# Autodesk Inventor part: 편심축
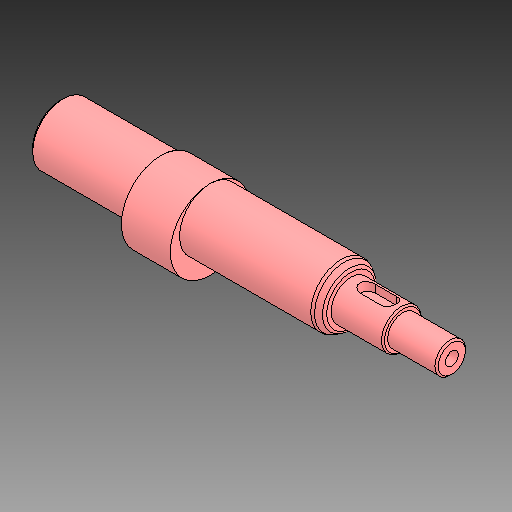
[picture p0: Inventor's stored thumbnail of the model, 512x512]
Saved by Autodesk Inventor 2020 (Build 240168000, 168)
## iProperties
Created: 2024-08
Part Number: 편심축
Material: 강철, 탄소
Document SubType Name: Modeling
Designer: 1강의실14
Density: 7.85 g/cm^3
Appearance: 기본값
Author: jhkim
Sending System: Autodesk Inventor 2025
Preprocessor: ST-DEVELOPER v20
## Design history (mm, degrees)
feature "솔리드1"
node "솔리드2"
